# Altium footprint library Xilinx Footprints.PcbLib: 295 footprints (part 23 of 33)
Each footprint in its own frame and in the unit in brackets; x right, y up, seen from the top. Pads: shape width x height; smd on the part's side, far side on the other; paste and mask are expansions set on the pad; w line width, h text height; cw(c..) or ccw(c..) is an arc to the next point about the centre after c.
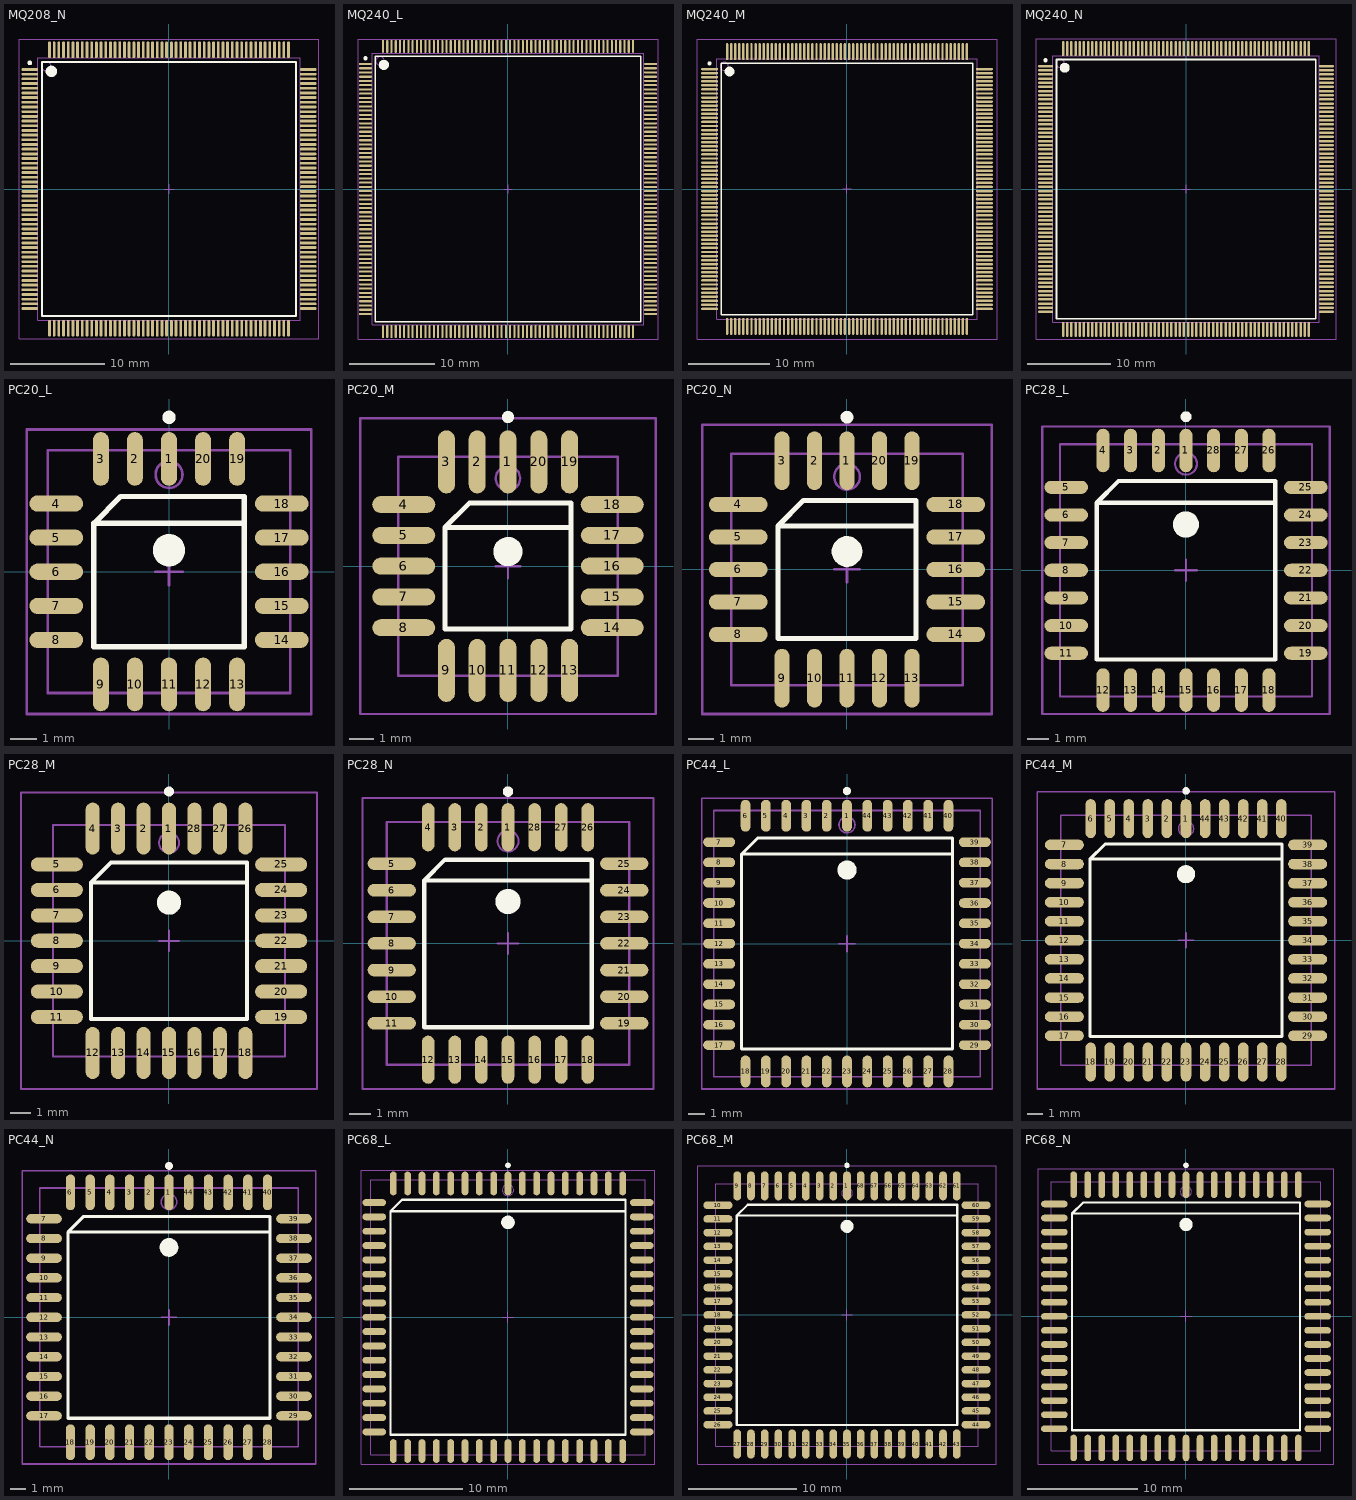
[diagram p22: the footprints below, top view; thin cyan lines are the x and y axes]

## MQ208_N [mm] "208-Pin Metal Quad Flat Pack (MQ208), IPC Medium Density"
height 4.1
pads (208):
  oval 1.8x0.3 smd: 1(-14.85,12.75) 2(-14.85,12.25) 3(-14.85,11.75) 4(-14.85,11.25) 5(-14.85,10.75) 6(-14.85,10.25) 7(-14.85,9.75) 8(-14.85,9.25) 9(-14.85,8.75) 10(-14.85,8.25) 11(-14.85,7.75) 12(-14.85,7.25) 13(-14.85,6.75) 14(-14.85,6.25) 15(-14.85,5.75) 16(-14.85,5.25) 17(-14.85,4.75) 18(-14.85,4.25) 19(-14.85,3.75) 20(-14.85,3.25) 21(-14.85,2.75) 22(-14.85,2.25) 23(-14.85,1.75) 24(-14.85,1.25) 25(-14.85,0.75) 26(-14.85,0.25) 27(-14.85,-0.25) 28(-14.85,-0.75) 29(-14.85,-1.25) 30(-14.85,-1.75) 31(-14.85,-2.25) 32(-14.85,-2.75) 33(-14.85,-3.25) 34(-14.85,-3.75) 35(-14.85,-4.25) 36(-14.85,-4.75) 37(-14.85,-5.25) 38(-14.85,-5.75) 39(-14.85,-6.25) 40(-14.85,-6.75) 41(-14.85,-7.25) 42(-14.85,-7.75) 43(-14.85,-8.25) 44(-14.85,-8.75) 45(-14.85,-9.25) 46(-14.85,-9.75) 47(-14.85,-10.25) 48(-14.85,-10.75) 49(-14.85,-11.25) 50(-14.85,-11.75) 51(-14.85,-12.25) 52(-14.85,-12.75) 105(14.85,-12.75) 106(14.85,-12.25) 107(14.85,-11.75) 108(14.85,-11.25) 109(14.85,-10.75) 110(14.85,-10.25) 111(14.85,-9.75) 112(14.85,-9.25) 113(14.85,-8.75) 114(14.85,-8.25) 115(14.85,-7.75) 116(14.85,-7.25) 117(14.85,-6.75) 118(14.85,-6.25) 119(14.85,-5.75) 120(14.85,-5.25) 121(14.85,-4.75) 122(14.85,-4.25) 123(14.85,-3.75) 124(14.85,-3.25) 125(14.85,-2.75) 126(14.85,-2.25) 127(14.85,-1.75) 128(14.85,-1.25) 129(14.85,-0.75) 130(14.85,-0.25) 131(14.85,0.25) 132(14.85,0.75) 133(14.85,1.25) 134(14.85,1.75) 135(14.85,2.25) 136(14.85,2.75) 137(14.85,3.25) 138(14.85,3.75) 139(14.85,4.25) 140(14.85,4.75) 141(14.85,5.25) 142(14.85,5.75) 143(14.85,6.25) 144(14.85,6.75) 145(14.85,7.25) 146(14.85,7.75) 147(14.85,8.25) 148(14.85,8.75) 149(14.85,9.25) 150(14.85,9.75) 151(14.85,10.25) 152(14.85,10.75) 153(14.85,11.25) 154(14.85,11.75) 155(14.85,12.25) 156(14.85,12.75)
  oval 0.3x1.8 smd: 53(-12.75,-14.85) 54(-12.25,-14.85) 55(-11.75,-14.85) 56(-11.25,-14.85) 57(-10.75,-14.85) 58(-10.25,-14.85) 59(-9.75,-14.85) 60(-9.25,-14.85) 61(-8.75,-14.85) 62(-8.25,-14.85) 63(-7.75,-14.85) 64(-7.25,-14.85) 65(-6.75,-14.85) 66(-6.25,-14.85) 67(-5.75,-14.85) 68(-5.25,-14.85) 69(-4.75,-14.85) 70(-4.25,-14.85) 71(-3.75,-14.85) 72(-3.25,-14.85) 73(-2.75,-14.85) 74(-2.25,-14.85) 75(-1.75,-14.85) 76(-1.25,-14.85) 77(-0.75,-14.85) 78(-0.25,-14.85) 79(0.25,-14.85) 80(0.75,-14.85) 81(1.25,-14.85) 82(1.75,-14.85) 83(2.25,-14.85) 84(2.75,-14.85) 85(3.25,-14.85) 86(3.75,-14.85) 87(4.25,-14.85) 88(4.75,-14.85) 89(5.25,-14.85) 90(5.75,-14.85) 91(6.25,-14.85) 92(6.75,-14.85) 93(7.25,-14.85) 94(7.75,-14.85) 95(8.25,-14.85) 96(8.75,-14.85) 97(9.25,-14.85) 98(9.75,-14.85) 99(10.25,-14.85) 100(10.75,-14.85) 101(11.25,-14.85) 102(11.75,-14.85) 103(12.25,-14.85) 104(12.75,-14.85) 157(12.75,14.85) 158(12.25,14.85) 159(11.75,14.85) 160(11.25,14.85) 161(10.75,14.85) 162(10.25,14.85) 163(9.75,14.85) 164(9.25,14.85) 165(8.75,14.85) 166(8.25,14.85) 167(7.75,14.85) 168(7.25,14.85) 169(6.75,14.85) 170(6.25,14.85) 171(5.75,14.85) 172(5.25,14.85) 173(4.75,14.85) 174(4.25,14.85) 175(3.75,14.85) 176(3.25,14.85) 177(2.75,14.85) 178(2.25,14.85) 179(1.75,14.85) 180(1.25,14.85) 181(0.75,14.85) 182(0.25,14.85) 183(-0.25,14.85) 184(-0.75,14.85) 185(-1.25,14.85) 186(-1.75,14.85) 187(-2.25,14.85) 188(-2.75,14.85) 189(-3.25,14.85) 190(-3.75,14.85) 191(-4.25,14.85) 192(-4.75,14.85) 193(-5.25,14.85) 194(-5.75,14.85) 195(-6.25,14.85) 196(-6.75,14.85) 197(-7.25,14.85) 198(-7.75,14.85) 199(-8.25,14.85) 200(-8.75,14.85) 201(-9.25,14.85) 202(-9.75,14.85) 203(-10.25,14.85) 204(-10.75,14.85) 205(-11.25,14.85) 206(-11.75,14.85) 207(-12.25,14.85) 208(-12.75,14.85)
Top Overlay:
  circle w0.6: c-12.55,12.55 r0.3
  circle w0.25: c-14.85,13.45 r0.125
  lines w0.2: -13.55,-13.55 13.55,-13.55 13.55,13.55 -13.55,13.55 -13.55,-13.55
Mechanical 13:
  circle w0.1: c-13.1,13.1 r0.5
  lines w0.1: -14,-14 14,-14 14,14 -14,14 -14,-14
Mechanical 15:
  lines w0.1: -0.5,0 0.5,0 ; 0,-0.5 0,0.5 ; -16,-16 16,-16 16,16 -16,16 -16,-16
3D body: height 4.1, standoff 0, extent -14,-14 14,14

## MQ240_L [mm] "240-Pin Metal Quad Flat Pack (MQ240), IPC High Density"
height 3.74
pads (240):
  oval 1.55x0.25 smd: 1(-16.825,14.75) 2(-16.825,14.25) 3(-16.825,13.75) 4(-16.825,13.25) 5(-16.825,12.75) 6(-16.825,12.25) 7(-16.825,11.75) 8(-16.825,11.25) 9(-16.825,10.75) 10(-16.825,10.25) 11(-16.825,9.75) 12(-16.825,9.25) 13(-16.825,8.75) 14(-16.825,8.25) 15(-16.825,7.75) 16(-16.825,7.25) 17(-16.825,6.75) 18(-16.825,6.25) 19(-16.825,5.75) 20(-16.825,5.25) 21(-16.825,4.75) 22(-16.825,4.25) 23(-16.825,3.75) 24(-16.825,3.25) 25(-16.825,2.75) 26(-16.825,2.25) 27(-16.825,1.75) 28(-16.825,1.25) 29(-16.825,0.75) 30(-16.825,0.25) 31(-16.825,-0.25) 32(-16.825,-0.75) 33(-16.825,-1.25) 34(-16.825,-1.75) 35(-16.825,-2.25) 36(-16.825,-2.75) 37(-16.825,-3.25) 38(-16.825,-3.75) 39(-16.825,-4.25) 40(-16.825,-4.75) 41(-16.825,-5.25) 42(-16.825,-5.75) 43(-16.825,-6.25) 44(-16.825,-6.75) 45(-16.825,-7.25) 46(-16.825,-7.75) 47(-16.825,-8.25) 48(-16.825,-8.75) 49(-16.825,-9.25) 50(-16.825,-9.75) 51(-16.825,-10.25) 52(-16.825,-10.75) 53(-16.825,-11.25) 54(-16.825,-11.75) 55(-16.825,-12.25) 56(-16.825,-12.75) 57(-16.825,-13.25) 58(-16.825,-13.75) 59(-16.825,-14.25) 60(-16.825,-14.75) 121(16.825,-14.75) 122(16.825,-14.25) 123(16.825,-13.75) 124(16.825,-13.25) 125(16.825,-12.75) 126(16.825,-12.25) 127(16.825,-11.75) 128(16.825,-11.25) 129(16.825,-10.75) 130(16.825,-10.25) 131(16.825,-9.75) 132(16.825,-9.25) 133(16.825,-8.75) 134(16.825,-8.25) 135(16.825,-7.75) 136(16.825,-7.25) 137(16.825,-6.75) 138(16.825,-6.25) 139(16.825,-5.75) 140(16.825,-5.25) 141(16.825,-4.75) 142(16.825,-4.25) 143(16.825,-3.75) 144(16.825,-3.25) 145(16.825,-2.75) 146(16.825,-2.25) 147(16.825,-1.75) 148(16.825,-1.25) 149(16.825,-0.75) 150(16.825,-0.25) 151(16.825,0.25) 152(16.825,0.75) 153(16.825,1.25) 154(16.825,1.75) 155(16.825,2.25) 156(16.825,2.75) 157(16.825,3.25) 158(16.825,3.75) 159(16.825,4.25) 160(16.825,4.75) 161(16.825,5.25) 162(16.825,5.75) 163(16.825,6.25) 164(16.825,6.75) 165(16.825,7.25) 166(16.825,7.75) 167(16.825,8.25) 168(16.825,8.75) 169(16.825,9.25) 170(16.825,9.75) 171(16.825,10.25) 172(16.825,10.75) 173(16.825,11.25) 174(16.825,11.75) 175(16.825,12.25) 176(16.825,12.75) 177(16.825,13.25) 178(16.825,13.75) 179(16.825,14.25) 180(16.825,14.75)
  oval 0.25x1.55 smd: 61(-14.75,-16.825) 62(-14.25,-16.825) 63(-13.75,-16.825) 64(-13.25,-16.825) 65(-12.75,-16.825) 66(-12.25,-16.825) 67(-11.75,-16.825) 68(-11.25,-16.825) 69(-10.75,-16.825) 70(-10.25,-16.825) 71(-9.75,-16.825) 72(-9.25,-16.825) 73(-8.75,-16.825) 74(-8.25,-16.825) 75(-7.75,-16.825) 76(-7.25,-16.825) 77(-6.75,-16.825) 78(-6.25,-16.825) 79(-5.75,-16.825) 80(-5.25,-16.825) 81(-4.75,-16.825) 82(-4.25,-16.825) 83(-3.75,-16.825) 84(-3.25,-16.825) 85(-2.75,-16.825) 86(-2.25,-16.825) 87(-1.75,-16.825) 88(-1.25,-16.825) 89(-0.75,-16.825) 90(-0.25,-16.825) 91(0.25,-16.825) 92(0.75,-16.825) 93(1.25,-16.825) 94(1.75,-16.825) 95(2.25,-16.825) 96(2.75,-16.825) 97(3.25,-16.825) 98(3.75,-16.825) 99(4.25,-16.825) 100(4.75,-16.825) 101(5.25,-16.825) 102(5.75,-16.825) 103(6.25,-16.825) 104(6.75,-16.825) 105(7.25,-16.825) 106(7.75,-16.825) 107(8.25,-16.825) 108(8.75,-16.825) 109(9.25,-16.825) 110(9.75,-16.825) 111(10.25,-16.825) 112(10.75,-16.825) 113(11.25,-16.825) 114(11.75,-16.825) 115(12.25,-16.825) 116(12.75,-16.825) 117(13.25,-16.825) 118(13.75,-16.825) 119(14.25,-16.825) 120(14.75,-16.825) 181(14.75,16.825) 182(14.25,16.825) 183(13.75,16.825) 184(13.25,16.825) 185(12.75,16.825) 186(12.25,16.825) 187(11.75,16.825) 188(11.25,16.825) 189(10.75,16.825) 190(10.25,16.825) 191(9.75,16.825) 192(9.25,16.825) 193(8.75,16.825) 194(8.25,16.825) 195(7.75,16.825) 196(7.25,16.825) 197(6.75,16.825) 198(6.25,16.825) 199(5.75,16.825) 200(5.25,16.825) 201(4.75,16.825) 202(4.25,16.825) 203(3.75,16.825) 204(3.25,16.825) 205(2.75,16.825) 206(2.25,16.825) 207(1.75,16.825) 208(1.25,16.825) 209(0.75,16.825) 210(0.25,16.825) 211(-0.25,16.825) 212(-0.75,16.825) 213(-1.25,16.825) 214(-1.75,16.825) 215(-2.25,16.825) 216(-2.75,16.825) 217(-3.25,16.825) 218(-3.75,16.825) 219(-4.25,16.825) 220(-4.75,16.825) 221(-5.25,16.825) 222(-5.75,16.825) 223(-6.25,16.825) 224(-6.75,16.825) 225(-7.25,16.825) 226(-7.75,16.825) 227(-8.25,16.825) 228(-8.75,16.825) 229(-9.25,16.825) 230(-9.75,16.825) 231(-10.25,16.825) 232(-10.75,16.825) 233(-11.25,16.825) 234(-11.75,16.825) 235(-12.25,16.825) 236(-12.75,16.825) 237(-13.25,16.825) 238(-13.75,16.825) 239(-14.25,16.825) 240(-14.75,16.825)
Top Overlay:
  circle w0.6: c-14.65,14.65 r0.3
  circle w0.25: c-16.825,15.425 r0.125
  lines w0.2: -15.65,-15.65 15.65,-15.65 15.65,15.65 -15.65,15.65 -15.65,-15.65
Mechanical 13:
  circle w0.1: c-15.1,15.1 r0.5
  lines w0.1: -16,-16 16,-16 16,16 -16,16 -16,-16
Mechanical 15:
  lines w0.1: -0.5,0 0.5,0 ; 0,-0.5 0,0.5 ; -17.7,-17.7 17.7,-17.7 17.7,17.7 -17.7,17.7 -17.7,-17.7
3D body: height 3.74, standoff 0, extent -16,-16 16,16

## MQ240_M [mm] "240-Pin Metal Quad Flat Pack (MQ240), IPC Low Density"
height 3.74
pads (240):
  oval 2.1x0.3 smd: 1(-16.9,14.75) 2(-16.9,14.25) 3(-16.9,13.75) 4(-16.9,13.25) 5(-16.9,12.75) 6(-16.9,12.25) 7(-16.9,11.75) 8(-16.9,11.25) 9(-16.9,10.75) 10(-16.9,10.25) 11(-16.9,9.75) 12(-16.9,9.25) 13(-16.9,8.75) 14(-16.9,8.25) 15(-16.9,7.75) 16(-16.9,7.25) 17(-16.9,6.75) 18(-16.9,6.25) 19(-16.9,5.75) 20(-16.9,5.25) 21(-16.9,4.75) 22(-16.9,4.25) 23(-16.9,3.75) 24(-16.9,3.25) 25(-16.9,2.75) 26(-16.9,2.25) 27(-16.9,1.75) 28(-16.9,1.25) 29(-16.9,0.75) 30(-16.9,0.25) 31(-16.9,-0.25) 32(-16.9,-0.75) 33(-16.9,-1.25) 34(-16.9,-1.75) 35(-16.9,-2.25) 36(-16.9,-2.75) 37(-16.9,-3.25) 38(-16.9,-3.75) 39(-16.9,-4.25) 40(-16.9,-4.75) 41(-16.9,-5.25) 42(-16.9,-5.75) 43(-16.9,-6.25) 44(-16.9,-6.75) 45(-16.9,-7.25) 46(-16.9,-7.75) 47(-16.9,-8.25) 48(-16.9,-8.75) 49(-16.9,-9.25) 50(-16.9,-9.75) 51(-16.9,-10.25) 52(-16.9,-10.75) 53(-16.9,-11.25) 54(-16.9,-11.75) 55(-16.9,-12.25) 56(-16.9,-12.75) 57(-16.9,-13.25) 58(-16.9,-13.75) 59(-16.9,-14.25) 60(-16.9,-14.75) 121(16.9,-14.75) 122(16.9,-14.25) 123(16.9,-13.75) 124(16.9,-13.25) 125(16.9,-12.75) 126(16.9,-12.25) 127(16.9,-11.75) 128(16.9,-11.25) 129(16.9,-10.75) 130(16.9,-10.25) 131(16.9,-9.75) 132(16.9,-9.25) 133(16.9,-8.75) 134(16.9,-8.25) 135(16.9,-7.75) 136(16.9,-7.25) 137(16.9,-6.75) 138(16.9,-6.25) 139(16.9,-5.75) 140(16.9,-5.25) 141(16.9,-4.75) 142(16.9,-4.25) 143(16.9,-3.75) 144(16.9,-3.25) 145(16.9,-2.75) 146(16.9,-2.25) 147(16.9,-1.75) 148(16.9,-1.25) 149(16.9,-0.75) 150(16.9,-0.25) 151(16.9,0.25) 152(16.9,0.75) 153(16.9,1.25) 154(16.9,1.75) 155(16.9,2.25) 156(16.9,2.75) 157(16.9,3.25) 158(16.9,3.75) 159(16.9,4.25) 160(16.9,4.75) 161(16.9,5.25) 162(16.9,5.75) 163(16.9,6.25) 164(16.9,6.75) 165(16.9,7.25) 166(16.9,7.75) 167(16.9,8.25) 168(16.9,8.75) 169(16.9,9.25) 170(16.9,9.75) 171(16.9,10.25) 172(16.9,10.75) 173(16.9,11.25) 174(16.9,11.75) 175(16.9,12.25) 176(16.9,12.75) 177(16.9,13.25) 178(16.9,13.75) 179(16.9,14.25) 180(16.9,14.75)
  oval 0.3x2.1 smd: 61(-14.75,-16.9) 62(-14.25,-16.9) 63(-13.75,-16.9) 64(-13.25,-16.9) 65(-12.75,-16.9) 66(-12.25,-16.9) 67(-11.75,-16.9) 68(-11.25,-16.9) 69(-10.75,-16.9) 70(-10.25,-16.9) 71(-9.75,-16.9) 72(-9.25,-16.9) 73(-8.75,-16.9) 74(-8.25,-16.9) 75(-7.75,-16.9) 76(-7.25,-16.9) 77(-6.75,-16.9) 78(-6.25,-16.9) 79(-5.75,-16.9) 80(-5.25,-16.9) 81(-4.75,-16.9) 82(-4.25,-16.9) 83(-3.75,-16.9) 84(-3.25,-16.9) 85(-2.75,-16.9) 86(-2.25,-16.9) 87(-1.75,-16.9) 88(-1.25,-16.9) 89(-0.75,-16.9) 90(-0.25,-16.9) 91(0.25,-16.9) 92(0.75,-16.9) 93(1.25,-16.9) 94(1.75,-16.9) 95(2.25,-16.9) 96(2.75,-16.9) 97(3.25,-16.9) 98(3.75,-16.9) 99(4.25,-16.9) 100(4.75,-16.9) 101(5.25,-16.9) 102(5.75,-16.9) 103(6.25,-16.9) 104(6.75,-16.9) 105(7.25,-16.9) 106(7.75,-16.9) 107(8.25,-16.9) 108(8.75,-16.9) 109(9.25,-16.9) 110(9.75,-16.9) 111(10.25,-16.9) 112(10.75,-16.9) 113(11.25,-16.9) 114(11.75,-16.9) 115(12.25,-16.9) 116(12.75,-16.9) 117(13.25,-16.9) 118(13.75,-16.9) 119(14.25,-16.9) 120(14.75,-16.9) 181(14.75,16.9) 182(14.25,16.9) 183(13.75,16.9) 184(13.25,16.9) 185(12.75,16.9) 186(12.25,16.9) 187(11.75,16.9) 188(11.25,16.9) 189(10.75,16.9) 190(10.25,16.9) 191(9.75,16.9) 192(9.25,16.9) 193(8.75,16.9) 194(8.25,16.9) 195(7.75,16.9) 196(7.25,16.9) 197(6.75,16.9) 198(6.25,16.9) 199(5.75,16.9) 200(5.25,16.9) 201(4.75,16.9) 202(4.25,16.9) 203(3.75,16.9) 204(3.25,16.9) 205(2.75,16.9) 206(2.25,16.9) 207(1.75,16.9) 208(1.25,16.9) 209(0.75,16.9) 210(0.25,16.9) 211(-0.25,16.9) 212(-0.75,16.9) 213(-1.25,16.9) 214(-1.75,16.9) 215(-2.25,16.9) 216(-2.75,16.9) 217(-3.25,16.9) 218(-3.75,16.9) 219(-4.25,16.9) 220(-4.75,16.9) 221(-5.25,16.9) 222(-5.75,16.9) 223(-6.25,16.9) 224(-6.75,16.9) 225(-7.25,16.9) 226(-7.75,16.9) 227(-8.25,16.9) 228(-8.75,16.9) 229(-9.25,16.9) 230(-9.75,16.9) 231(-10.25,16.9) 232(-10.75,16.9) 233(-11.25,16.9) 234(-11.75,16.9) 235(-12.25,16.9) 236(-12.75,16.9) 237(-13.25,16.9) 238(-13.75,16.9) 239(-14.25,16.9) 240(-14.75,16.9)
Top Overlay:
  circle w0.6: c-14.45,14.45 r0.3
  circle w0.25: c-16.9,15.45 r0.125
  lines w0.2: -15.45,-15.45 15.45,-15.45 15.45,15.45 -15.45,15.45 -15.45,-15.45
Mechanical 13:
  circle w0.1: c-15.1,15.1 r0.5
  lines w0.1: -16,-16 16,-16 16,16 -16,16 -16,-16
Mechanical 15:
  lines w0.1: -0.5,0 0.5,0 ; 0,-0.5 0,0.5 ; -18.45,-18.45 18.45,-18.45 18.45,18.45 -18.45,18.45 -18.45,-18.45
3D body: height 3.74, standoff 0, extent -16,-16 16,16

## MQ240_N [mm] "240-Pin Metal Quad Flat Pack (MQ240), IPC Medium Density"
height 3.74
pads (240):
  oval 1.8x0.3 smd: 1(-16.85,14.75) 2(-16.85,14.25) 3(-16.85,13.75) 4(-16.85,13.25) 5(-16.85,12.75) 6(-16.85,12.25) 7(-16.85,11.75) 8(-16.85,11.25) 9(-16.85,10.75) 10(-16.85,10.25) 11(-16.85,9.75) 12(-16.85,9.25) 13(-16.85,8.75) 14(-16.85,8.25) 15(-16.85,7.75) 16(-16.85,7.25) 17(-16.85,6.75) 18(-16.85,6.25) 19(-16.85,5.75) 20(-16.85,5.25) 21(-16.85,4.75) 22(-16.85,4.25) 23(-16.85,3.75) 24(-16.85,3.25) 25(-16.85,2.75) 26(-16.85,2.25) 27(-16.85,1.75) 28(-16.85,1.25) 29(-16.85,0.75) 30(-16.85,0.25) 31(-16.85,-0.25) 32(-16.85,-0.75) 33(-16.85,-1.25) 34(-16.85,-1.75) 35(-16.85,-2.25) 36(-16.85,-2.75) 37(-16.85,-3.25) 38(-16.85,-3.75) 39(-16.85,-4.25) 40(-16.85,-4.75) 41(-16.85,-5.25) 42(-16.85,-5.75) 43(-16.85,-6.25) 44(-16.85,-6.75) 45(-16.85,-7.25) 46(-16.85,-7.75) 47(-16.85,-8.25) 48(-16.85,-8.75) 49(-16.85,-9.25) 50(-16.85,-9.75) 51(-16.85,-10.25) 52(-16.85,-10.75) 53(-16.85,-11.25) 54(-16.85,-11.75) 55(-16.85,-12.25) 56(-16.85,-12.75) 57(-16.85,-13.25) 58(-16.85,-13.75) 59(-16.85,-14.25) 60(-16.85,-14.75) 121(16.85,-14.75) 122(16.85,-14.25) 123(16.85,-13.75) 124(16.85,-13.25) 125(16.85,-12.75) 126(16.85,-12.25) 127(16.85,-11.75) 128(16.85,-11.25) 129(16.85,-10.75) 130(16.85,-10.25) 131(16.85,-9.75) 132(16.85,-9.25) 133(16.85,-8.75) 134(16.85,-8.25) 135(16.85,-7.75) 136(16.85,-7.25) 137(16.85,-6.75) 138(16.85,-6.25) 139(16.85,-5.75) 140(16.85,-5.25) 141(16.85,-4.75) 142(16.85,-4.25) 143(16.85,-3.75) 144(16.85,-3.25) 145(16.85,-2.75) 146(16.85,-2.25) 147(16.85,-1.75) 148(16.85,-1.25) 149(16.85,-0.75) 150(16.85,-0.25) 151(16.85,0.25) 152(16.85,0.75) 153(16.85,1.25) 154(16.85,1.75) 155(16.85,2.25) 156(16.85,2.75) 157(16.85,3.25) 158(16.85,3.75) 159(16.85,4.25) 160(16.85,4.75) 161(16.85,5.25) 162(16.85,5.75) 163(16.85,6.25) 164(16.85,6.75) 165(16.85,7.25) 166(16.85,7.75) 167(16.85,8.25) 168(16.85,8.75) 169(16.85,9.25) 170(16.85,9.75) 171(16.85,10.25) 172(16.85,10.75) 173(16.85,11.25) 174(16.85,11.75) 175(16.85,12.25) 176(16.85,12.75) 177(16.85,13.25) 178(16.85,13.75) 179(16.85,14.25) 180(16.85,14.75)
  oval 0.3x1.8 smd: 61(-14.75,-16.85) 62(-14.25,-16.85) 63(-13.75,-16.85) 64(-13.25,-16.85) 65(-12.75,-16.85) 66(-12.25,-16.85) 67(-11.75,-16.85) 68(-11.25,-16.85) 69(-10.75,-16.85) 70(-10.25,-16.85) 71(-9.75,-16.85) 72(-9.25,-16.85) 73(-8.75,-16.85) 74(-8.25,-16.85) 75(-7.75,-16.85) 76(-7.25,-16.85) 77(-6.75,-16.85) 78(-6.25,-16.85) 79(-5.75,-16.85) 80(-5.25,-16.85) 81(-4.75,-16.85) 82(-4.25,-16.85) 83(-3.75,-16.85) 84(-3.25,-16.85) 85(-2.75,-16.85) 86(-2.25,-16.85) 87(-1.75,-16.85) 88(-1.25,-16.85) 89(-0.75,-16.85) 90(-0.25,-16.85) 91(0.25,-16.85) 92(0.75,-16.85) 93(1.25,-16.85) 94(1.75,-16.85) 95(2.25,-16.85) 96(2.75,-16.85) 97(3.25,-16.85) 98(3.75,-16.85) 99(4.25,-16.85) 100(4.75,-16.85) 101(5.25,-16.85) 102(5.75,-16.85) 103(6.25,-16.85) 104(6.75,-16.85) 105(7.25,-16.85) 106(7.75,-16.85) 107(8.25,-16.85) 108(8.75,-16.85) 109(9.25,-16.85) 110(9.75,-16.85) 111(10.25,-16.85) 112(10.75,-16.85) 113(11.25,-16.85) 114(11.75,-16.85) 115(12.25,-16.85) 116(12.75,-16.85) 117(13.25,-16.85) 118(13.75,-16.85) 119(14.25,-16.85) 120(14.75,-16.85) 181(14.75,16.85) 182(14.25,16.85) 183(13.75,16.85) 184(13.25,16.85) 185(12.75,16.85) 186(12.25,16.85) 187(11.75,16.85) 188(11.25,16.85) 189(10.75,16.85) 190(10.25,16.85) 191(9.75,16.85) 192(9.25,16.85) 193(8.75,16.85) 194(8.25,16.85) 195(7.75,16.85) 196(7.25,16.85) 197(6.75,16.85) 198(6.25,16.85) 199(5.75,16.85) 200(5.25,16.85) 201(4.75,16.85) 202(4.25,16.85) 203(3.75,16.85) 204(3.25,16.85) 205(2.75,16.85) 206(2.25,16.85) 207(1.75,16.85) 208(1.25,16.85) 209(0.75,16.85) 210(0.25,16.85) 211(-0.25,16.85) 212(-0.75,16.85) 213(-1.25,16.85) 214(-1.75,16.85) 215(-2.25,16.85) 216(-2.75,16.85) 217(-3.25,16.85) 218(-3.75,16.85) 219(-4.25,16.85) 220(-4.75,16.85) 221(-5.25,16.85) 222(-5.75,16.85) 223(-6.25,16.85) 224(-6.75,16.85) 225(-7.25,16.85) 226(-7.75,16.85) 227(-8.25,16.85) 228(-8.75,16.85) 229(-9.25,16.85) 230(-9.75,16.85) 231(-10.25,16.85) 232(-10.75,16.85) 233(-11.25,16.85) 234(-11.75,16.85) 235(-12.25,16.85) 236(-12.75,16.85) 237(-13.25,16.85) 238(-13.75,16.85) 239(-14.25,16.85) 240(-14.75,16.85)
Top Overlay:
  circle w0.6: c-14.55,14.55 r0.3
  circle w0.25: c-16.85,15.45 r0.125
  lines w0.2: -15.55,-15.55 15.55,-15.55 15.55,15.55 -15.55,15.55 -15.55,-15.55
Mechanical 13:
  circle w0.1: c-15.1,15.1 r0.5
  lines w0.1: -16,-16 16,-16 16,16 -16,16 -16,-16
Mechanical 15:
  lines w0.1: -0.5,0 0.5,0 ; 0,-0.5 0,0.5 ; -18,-18 18,-18 18,18 -18,18 -18,-18
3D body: height 3.74, standoff 0, extent -16,-16 16,16

## PC20_L [mm] "20-Pin Plastic Leaded Chip Carrier (PC20), IPC High Density"
height 4.58
pads (20):
  oval 0.6x2 smd: 1(0,4.2) 2(-1.27,4.2) 3(-2.54,4.2) 9(-2.54,-4.2) 10(-1.27,-4.2) 11(0,-4.2) 12(1.27,-4.2) 13(2.54,-4.2) 19(2.54,4.2) 20(1.27,4.2)
  oval 2x0.6 smd: 4(-4.2,2.54) 5(-4.2,1.27) 6(-4.2,0) 7(-4.2,-1.27) 8(-4.2,-2.54) 14(4.2,-2.54) 15(4.2,-1.27) 16(4.2,0) 17(4.2,1.27) 18(4.2,2.54)
Top Overlay:
  circle w0.25: c0,5.75 r0.125
  circle w0.6: c0,0.8 r0.3
  lines w0.2: 2.8,1.8 -2.8,1.8 ; -2.8,1.8 -1.8,2.8 2.8,2.8 2.8,-2.8 -2.8,-2.8 -2.8,1.8
Mechanical 13:
  circle w0.1: c0,3.62 r0.5
  lines w0.1: -4.52,-4.52 -4.52,4.52 4.52,4.52 4.52,-4.52 -4.52,-4.52
Mechanical 15:
  lines w0.1: -0.5,0 0.5,0 ; 0,-0.5 0,0.5 ; -5.3,-5.3 -5.3,5.3 5.3,5.3 5.3,-5.3 -5.3,-5.3
3D body: height 4.58, standoff 0, extent -4.52,-4.52 4.52,4.52

## PC20_M [mm] "20-Pin Plastic Leaded Chip Carrier (PC20), IPC Low Density"
height 4.58
pads (20):
  oval 0.7x2.6 smd: 1(0,4.3) 2(-1.27,4.3) 3(-2.54,4.3) 9(-2.54,-4.3) 10(-1.27,-4.3) 11(0,-4.3) 12(1.27,-4.3) 13(2.54,-4.3) 19(2.54,4.3) 20(1.27,4.3)
  oval 2.6x0.7 smd: 4(-4.3,2.54) 5(-4.3,1.27) 6(-4.3,0) 7(-4.3,-1.27) 8(-4.3,-2.54) 14(4.3,-2.54) 15(4.3,-1.27) 16(4.3,0) 17(4.3,1.27) 18(4.3,2.54)
Top Overlay:
  circle w0.25: c0,6.15 r0.125
  circle w0.6: c0,0.6 r0.3
  lines w0.2: 2.6,1.6 -2.6,1.6 ; -2.6,1.6 -1.6,2.6 2.6,2.6 2.6,-2.6 -2.6,-2.6 -2.6,1.6
Mechanical 13:
  circle w0.1: c0,3.62 r0.5
  lines w0.1: -4.52,-4.52 -4.52,4.52 4.52,4.52 4.52,-4.52 -4.52,-4.52
Mechanical 15:
  lines w0.1: -0.5,0 0.5,0 ; 0,-0.5 0,0.5 ; -6.1,-6.1 -6.1,6.1 6.1,6.1 6.1,-6.1 -6.1,-6.1
3D body: height 4.58, standoff 0, extent -4.52,-4.52 4.52,4.52

## PC20_N [mm] "20-Pin Plastic Leaded Chip Carrier (PC20), IPC Medium Density"
height 4.58
pads (20):
  oval 0.6x2.3 smd: 1(0,4.25) 2(-1.27,4.25) 3(-2.54,4.25) 9(-2.54,-4.25) 10(-1.27,-4.25) 11(0,-4.25) 12(1.27,-4.25) 13(2.54,-4.25) 19(2.54,4.25) 20(1.27,4.25)
  oval 2.3x0.6 smd: 4(-4.25,2.54) 5(-4.25,1.27) 6(-4.25,0) 7(-4.25,-1.27) 8(-4.25,-2.54) 14(4.25,-2.54) 15(4.25,-1.27) 16(4.25,0) 17(4.25,1.27) 18(4.25,2.54)
Top Overlay:
  circle w0.6: c0,0.7 r0.3
  circle w0.25: c0,5.95 r0.125
  lines w0.2: 2.7,1.7 -2.7,1.7 ; -2.7,1.7 -2.7,-2.7 2.7,-2.7 2.7,2.7 -1.7,2.7 -2.7,1.7
Mechanical 13:
  circle w0.1: c0,3.62 r0.5
  lines w0.1: -4.52,-4.52 4.52,-4.52 4.52,4.52 -4.52,4.52 -4.52,-4.52
Mechanical 15:
  lines w0.1: -0.5,0 0.5,0 ; 0,-0.5 0,0.5 ; -5.65,-5.65 5.65,-5.65 5.65,5.65 -5.65,5.65 -5.65,-5.65
3D body: height 4.58, standoff 0, extent -4.52,-4.52 4.52,4.52

## PC28_L [mm] "28-Pin Plastic Leaded Chip Carrier (PC28), IPC High Density"
height 4.58
pads (28):
  oval 0.6x2 smd: 1(0,5.5) 2(-1.27,5.5) 3(-2.54,5.5) 4(-3.81,5.5) 12(-3.81,-5.5) 13(-2.54,-5.5) 14(-1.27,-5.5) 15(0,-5.5) 16(1.27,-5.5) 17(2.54,-5.5) 18(3.81,-5.5) 26(3.81,5.5) 27(2.54,5.5) 28(1.27,5.5)
  oval 2x0.6 smd: 5(-5.5,3.81) 6(-5.5,2.54) 7(-5.5,1.27) 8(-5.5,0) 9(-5.5,-1.27) 10(-5.5,-2.54) 11(-5.5,-3.81) 19(5.5,-3.81) 20(5.5,-2.54) 21(5.5,-1.27) 22(5.5,0) 23(5.5,1.27) 24(5.5,2.54) 25(5.5,3.81)
Top Overlay:
  circle w0.25: c0,7.05 r0.125
  circle w0.6: c0,2.1 r0.3
  lines w0.2: 4.1,3.1 -4.1,3.1 ; -4.1,3.1 -3.1,4.1 4.1,4.1 4.1,-4.1 -4.1,-4.1 -4.1,3.1
Mechanical 13:
  circle w0.1: c0,4.89 r0.5
  lines w0.1: -5.79,-5.79 -5.79,5.79 5.79,5.79 5.79,-5.79 -5.79,-5.79
Mechanical 15:
  lines w0.1: -0.5,0 0.5,0 ; 0,-0.5 0,0.5 ; -6.6,-6.6 -6.6,6.6 6.6,6.6 6.6,-6.6 -6.6,-6.6
3D body: height 4.58, standoff 0, extent -5.79,-5.79 5.79,5.79

## PC28_M [mm] "28-Pin Plastic Leaded Chip Carrier (PC28), IPC Low Density"
height 4.58
pads (28):
  oval 0.7x2.6 smd: 1(0,5.6) 2(-1.27,5.6) 3(-2.54,5.6) 4(-3.81,5.6) 12(-3.81,-5.6) 13(-2.54,-5.6) 14(-1.27,-5.6) 15(0,-5.6) 16(1.27,-5.6) 17(2.54,-5.6) 18(3.81,-5.6) 26(3.81,5.6) 27(2.54,5.6) 28(1.27,5.6)
  oval 2.6x0.7 smd: 5(-5.6,3.81) 6(-5.6,2.54) 7(-5.6,1.27) 8(-5.6,0) 9(-5.6,-1.27) 10(-5.6,-2.54) 11(-5.6,-3.81) 19(5.6,-3.81) 20(5.6,-2.54) 21(5.6,-1.27) 22(5.6,0) 23(5.6,1.27) 24(5.6,2.54) 25(5.6,3.81)
Top Overlay:
  circle w0.25: c0,7.45 r0.125
  circle w0.6: c0,1.9 r0.3
  lines w0.2: 3.9,2.9 -3.9,2.9 ; -3.9,2.9 -2.9,3.9 3.9,3.9 3.9,-3.9 -3.9,-3.9 -3.9,2.9
Mechanical 13:
  circle w0.1: c0,4.89 r0.5
  lines w0.1: -5.79,-5.79 -5.79,5.79 5.79,5.79 5.79,-5.79 -5.79,-5.79
Mechanical 15:
  lines w0.1: -0.5,0 0.5,0 ; 0,-0.5 0,0.5 ; -7.4,-7.4 -7.4,7.4 7.4,7.4 7.4,-7.4 -7.4,-7.4
3D body: height 4.58, standoff 0, extent -5.79,-5.79 5.79,5.79

## PC28_N [mm] "28-Pin Plastic Leaded Chip Carrier (PC28), IPC Medium Density"
height 4.58
pads (28):
  oval 0.6x2.3 smd: 1(0,5.55) 2(-1.27,5.55) 3(-2.54,5.55) 4(-3.81,5.55) 12(-3.81,-5.55) 13(-2.54,-5.55) 14(-1.27,-5.55) 15(0,-5.55) 16(1.27,-5.55) 17(2.54,-5.55) 18(3.81,-5.55) 26(3.81,5.55) 27(2.54,5.55) 28(1.27,5.55)
  oval 2.3x0.6 smd: 5(-5.55,3.81) 6(-5.55,2.54) 7(-5.55,1.27) 8(-5.55,0) 9(-5.55,-1.27) 10(-5.55,-2.54) 11(-5.55,-3.81) 19(5.55,-3.81) 20(5.55,-2.54) 21(5.55,-1.27) 22(5.55,0) 23(5.55,1.27) 24(5.55,2.54) 25(5.55,3.81)
Top Overlay:
  circle w0.25: c0,7.25 r0.125
  circle w0.6: c0,2 r0.3
  lines w0.2: 4,3 -4,3 ; -4,3 -3,4 4,4 4,-4 -4,-4 -4,3
Mechanical 13:
  circle w0.1: c0,4.89 r0.5
  lines w0.1: -5.79,-5.79 -5.79,5.79 5.79,5.79 5.79,-5.79 -5.79,-5.79
Mechanical 15:
  lines w0.1: -0.5,0 0.5,0 ; 0,-0.5 0,0.5 ; -6.95,-6.95 -6.95,6.95 6.95,6.95 6.95,-6.95 -6.95,-6.95
3D body: height 4.58, standoff 0, extent -5.79,-5.79 5.79,5.79

## PC44_L [mm] "44-Pin Plastic Leaded Chip Carrier (PC44), IPC High Density"
height 4.58
pads (44):
  oval 0.6x2 smd: 1(0,8) 2(-1.27,8) 3(-2.54,8) 4(-3.81,8) 5(-5.08,8) 6(-6.35,8) 18(-6.35,-8) 19(-5.08,-8) 20(-3.81,-8) 21(-2.54,-8) 22(-1.27,-8) 23(0,-8) 24(1.27,-8) 25(2.54,-8) 26(3.81,-8) 27(5.08,-8) 28(6.35,-8) 40(6.35,8) 41(5.08,8) 42(3.81,8) 43(2.54,8) 44(1.27,8)
  oval 2x0.6 smd: 7(-8,6.35) 8(-8,5.08) 9(-8,3.81) 10(-8,2.54) 11(-8,1.27) 12(-8,0) 13(-8,-1.27) 14(-8,-2.54) 15(-8,-3.81) 16(-8,-5.08) 17(-8,-6.35) 29(8,-6.35) 30(8,-5.08) 31(8,-3.81) 32(8,-2.54) 33(8,-1.27) 34(8,0) 35(8,1.27) 36(8,2.54) 37(8,3.81) 38(8,5.08) 39(8,6.35)
Top Overlay:
  circle w0.25: c0,9.55 r0.125
  circle w0.6: c0,4.6 r0.3
  lines w0.2: 6.6,5.6 -6.6,5.6 ; -6.6,5.6 -5.6,6.6 6.6,6.6 6.6,-6.6 -6.6,-6.6 -6.6,5.6
Mechanical 13:
  circle w0.1: c0,7.43 r0.5
  lines w0.1: -8.33,-8.33 -8.33,8.33 8.33,8.33 8.33,-8.33 -8.33,-8.33
Mechanical 15:
  lines w0.1: -0.5,0 0.5,0 ; 0,-0.5 0,0.5 ; -9.1,-9.1 -9.1,9.1 9.1,9.1 9.1,-9.1 -9.1,-9.1
3D body: height 4.58, standoff 0, extent -8.33,-8.33 8.33,8.33

## PC44_M [mm] "44-Pin Plastic Leaded Chip Carrier (PC44), IPC Low Density"
height 4.58
pads (44):
  oval 0.7x2.6 smd: 1(0,8.1) 2(-1.27,8.1) 3(-2.54,8.1) 4(-3.81,8.1) 5(-5.08,8.1) 6(-6.35,8.1) 18(-6.35,-8.1) 19(-5.08,-8.1) 20(-3.81,-8.1) 21(-2.54,-8.1) 22(-1.27,-8.1) 23(0,-8.1) 24(1.27,-8.1) 25(2.54,-8.1) 26(3.81,-8.1) 27(5.08,-8.1) 28(6.35,-8.1) 40(6.35,8.1) 41(5.08,8.1) 42(3.81,8.1) 43(2.54,8.1) 44(1.27,8.1)
  oval 2.6x0.7 smd: 7(-8.1,6.35) 8(-8.1,5.08) 9(-8.1,3.81) 10(-8.1,2.54) 11(-8.1,1.27) 12(-8.1,0) 13(-8.1,-1.27) 14(-8.1,-2.54) 15(-8.1,-3.81) 16(-8.1,-5.08) 17(-8.1,-6.35) 29(8.1,-6.35) 30(8.1,-5.08) 31(8.1,-3.81) 32(8.1,-2.54) 33(8.1,-1.27) 34(8.1,0) 35(8.1,1.27) 36(8.1,2.54) 37(8.1,3.81) 38(8.1,5.08) 39(8.1,6.35)
Top Overlay:
  circle w0.25: c0,9.95 r0.125
  circle w0.6: c0,4.4 r0.3
  lines w0.2: 6.4,5.4 -6.4,5.4 ; -6.4,5.4 -5.4,6.4 6.4,6.4 6.4,-6.4 -6.4,-6.4 -6.4,5.4
Mechanical 13:
  circle w0.1: c0,7.43 r0.5
  lines w0.1: -8.33,-8.33 -8.33,8.33 8.33,8.33 8.33,-8.33 -8.33,-8.33
Mechanical 15:
  lines w0.1: -0.5,0 0.5,0 ; 0,-0.5 0,0.5 ; -9.9,-9.9 -9.9,9.9 9.9,9.9 9.9,-9.9 -9.9,-9.9
3D body: height 4.58, standoff 0, extent -8.33,-8.33 8.33,8.33

## PC44_N [mm] "44-Pin Plastic Leaded Chip Carrier (PC44), IPC Medium Density"
height 4.58
pads (44):
  oval 0.6x2.3 smd: 1(0,8.05) 2(-1.27,8.05) 3(-2.54,8.05) 4(-3.81,8.05) 5(-5.08,8.05) 6(-6.35,8.05) 18(-6.35,-8.05) 19(-5.08,-8.05) 20(-3.81,-8.05) 21(-2.54,-8.05) 22(-1.27,-8.05) 23(0,-8.05) 24(1.27,-8.05) 25(2.54,-8.05) 26(3.81,-8.05) 27(5.08,-8.05) 28(6.35,-8.05) 40(6.35,8.05) 41(5.08,8.05) 42(3.81,8.05) 43(2.54,8.05) 44(1.27,8.05)
  oval 2.3x0.6 smd: 7(-8.05,6.35) 8(-8.05,5.08) 9(-8.05,3.81) 10(-8.05,2.54) 11(-8.05,1.27) 12(-8.05,0) 13(-8.05,-1.27) 14(-8.05,-2.54) 15(-8.05,-3.81) 16(-8.05,-5.08) 17(-8.05,-6.35) 29(8.05,-6.35) 30(8.05,-5.08) 31(8.05,-3.81) 32(8.05,-2.54) 33(8.05,-1.27) 34(8.05,0) 35(8.05,1.27) 36(8.05,2.54) 37(8.05,3.81) 38(8.05,5.08) 39(8.05,6.35)
Top Overlay:
  circle w0.25: c0,9.75 r0.125
  circle w0.6: c0,4.5 r0.3
  lines w0.2: 6.5,5.5 -6.5,5.5 ; -6.5,5.5 -5.5,6.5 6.5,6.5 6.5,-6.5 -6.5,-6.5 -6.5,5.5
Mechanical 13:
  circle w0.1: c0,7.43 r0.5
  lines w0.1: -8.33,-8.33 -8.33,8.33 8.33,8.33 8.33,-8.33 -8.33,-8.33
Mechanical 15:
  lines w0.1: -0.5,0 0.5,0 ; 0,-0.5 0,0.5 ; -9.45,-9.45 -9.45,9.45 9.45,9.45 9.45,-9.45 -9.45,-9.45
3D body: height 4.58, standoff 0, extent -8.33,-8.33 8.33,8.33

## PC68_L [mm] "68-Pin Plastic Leaded Chip Carrier (PC68), IPC High Density"
height 5.08
pads (68):
  oval 0.6x2.1 smd: 1(0,11.85) 2(-1.27,11.85) 3(-2.54,11.85) 4(-3.81,11.85) 5(-5.08,11.85) 6(-6.35,11.85) 7(-7.62,11.85) 8(-8.89,11.85) 9(-10.16,11.85) 27(-10.16,-11.85) 28(-8.89,-11.85) 29(-7.62,-11.85) 30(-6.35,-11.85) 31(-5.08,-11.85) 32(-3.81,-11.85) 33(-2.54,-11.85) 34(-1.27,-11.85) 35(0,-11.85) 36(1.27,-11.85) 37(2.54,-11.85) 38(3.81,-11.85) 39(5.08,-11.85) 40(6.35,-11.85) 41(7.62,-11.85) 42(8.89,-11.85) 43(10.16,-11.85) 61(10.16,11.85) 62(8.89,11.85) 63(7.62,11.85) 64(6.35,11.85) 65(5.08,11.85) 66(3.81,11.85) 67(2.54,11.85) 68(1.27,11.85)
  oval 2.1x0.6 smd: 10(-11.85,10.16) 11(-11.85,8.89) 12(-11.85,7.62) 13(-11.85,6.35) 14(-11.85,5.08) 15(-11.85,3.81) 16(-11.85,2.54) 17(-11.85,1.27) 18(-11.85,0) 19(-11.85,-1.27) 20(-11.85,-2.54) 21(-11.85,-3.81) 22(-11.85,-5.08) 23(-11.85,-6.35) 24(-11.85,-7.62) 25(-11.85,-8.89) 26(-11.85,-10.16) 44(11.85,-10.16) 45(11.85,-8.89) 46(11.85,-7.62) 47(11.85,-6.35) 48(11.85,-5.08) 49(11.85,-3.81) 50(11.85,-2.54) 51(11.85,-1.27) 52(11.85,0) 53(11.85,1.27) 54(11.85,2.54) 55(11.85,3.81) 56(11.85,5.08) 57(11.85,6.35) 58(11.85,7.62) 59(11.85,8.89) 60(11.85,10.16)
Top Overlay:
  circle w0.6: c0,8.4 r0.3
  circle w0.25: c0,13.45 r0.125
  lines w0.2: 10.4,9.4 -10.4,9.4 ; -10.4,9.4 -10.4,-10.4 10.4,-10.4 10.4,10.4 -9.4,10.4 -10.4,9.4
Mechanical 13:
  circle w0.1: c0,11.265 r0.5
  lines w0.1: -12.165,-12.165 12.165,-12.165 12.165,12.165 -12.165,12.165 -12.165,-12.165
Mechanical 15:
  lines w0.1: -0.5,0 0.5,0 ; 0,-0.5 0,0.5 ; -13,-13 13,-13 13,13 -13,13 -13,-13
3D body: height 5.08, standoff 0, extent -12.165,-12.165 12.165,12.165

## PC68_M [mm] "68-Pin Plastic Leaded Chip Carrier (PC68), IPC Low Density"
height 5.08
pads (68):
  oval 0.7x2.7 smd: 1(0,11.95) 2(-1.27,11.95) 3(-2.54,11.95) 4(-3.81,11.95) 5(-5.08,11.95) 6(-6.35,11.95) 7(-7.62,11.95) 8(-8.89,11.95) 9(-10.16,11.95) 27(-10.16,-11.95) 28(-8.89,-11.95) 29(-7.62,-11.95) 30(-6.35,-11.95) 31(-5.08,-11.95) 32(-3.81,-11.95) 33(-2.54,-11.95) 34(-1.27,-11.95) 35(0,-11.95) 36(1.27,-11.95) 37(2.54,-11.95) 38(3.81,-11.95) 39(5.08,-11.95) 40(6.35,-11.95) 41(7.62,-11.95) 42(8.89,-11.95) 43(10.16,-11.95) 61(10.16,11.95) 62(8.89,11.95) 63(7.62,11.95) 64(6.35,11.95) 65(5.08,11.95) 66(3.81,11.95) 67(2.54,11.95) 68(1.27,11.95)
  oval 2.7x0.7 smd: 10(-11.95,10.16) 11(-11.95,8.89) 12(-11.95,7.62) 13(-11.95,6.35) 14(-11.95,5.08) 15(-11.95,3.81) 16(-11.95,2.54) 17(-11.95,1.27) 18(-11.95,0) 19(-11.95,-1.27) 20(-11.95,-2.54) 21(-11.95,-3.81) 22(-11.95,-5.08) 23(-11.95,-6.35) 24(-11.95,-7.62) 25(-11.95,-8.89) 26(-11.95,-10.16) 44(11.95,-10.16) 45(11.95,-8.89) 46(11.95,-7.62) 47(11.95,-6.35) 48(11.95,-5.08) 49(11.95,-3.81) 50(11.95,-2.54) 51(11.95,-1.27) 52(11.95,0) 53(11.95,1.27) 54(11.95,2.54) 55(11.95,3.81) 56(11.95,5.08) 57(11.95,6.35) 58(11.95,7.62) 59(11.95,8.89) 60(11.95,10.16)
Top Overlay:
  circle w0.25: c0,13.85 r0.125
  circle w0.6: c0,8.2 r0.3
  lines w0.2: 10.2,9.2 -10.2,9.2 ; -10.2,9.2 -9.2,10.2 10.2,10.2 10.2,-10.2 -10.2,-10.2 -10.2,9.2
Mechanical 13:
  circle w0.1: c0,11.265 r0.5
  lines w0.1: -12.165,-12.165 -12.165,12.165 12.165,12.165 12.165,-12.165 -12.165,-12.165
Mechanical 15:
  lines w0.1: -0.5,0 0.5,0 ; 0,-0.5 0,0.5 ; -13.8,-13.8 -13.8,13.8 13.8,13.8 13.8,-13.8 -13.8,-13.8
3D body: height 5.08, standoff 0, extent -12.165,-12.165 12.165,12.165

## PC68_N [mm] "68-Pin Plastic Leaded Chip Carrier (PC68), IPC Medium Density"
height 5.08
pads (68):
  oval 0.6x2.4 smd: 1(0,11.9) 2(-1.27,11.9) 3(-2.54,11.9) 4(-3.81,11.9) 5(-5.08,11.9) 6(-6.35,11.9) 7(-7.62,11.9) 8(-8.89,11.9) 9(-10.16,11.9) 27(-10.16,-11.9) 28(-8.89,-11.9) 29(-7.62,-11.9) 30(-6.35,-11.9) 31(-5.08,-11.9) 32(-3.81,-11.9) 33(-2.54,-11.9) 34(-1.27,-11.9) 35(0,-11.9) 36(1.27,-11.9) 37(2.54,-11.9) 38(3.81,-11.9) 39(5.08,-11.9) 40(6.35,-11.9) 41(7.62,-11.9) 42(8.89,-11.9) 43(10.16,-11.9) 61(10.16,11.9) 62(8.89,11.9) 63(7.62,11.9) 64(6.35,11.9) 65(5.08,11.9) 66(3.81,11.9) 67(2.54,11.9) 68(1.27,11.9)
  oval 2.4x0.6 smd: 10(-11.9,10.16) 11(-11.9,8.89) 12(-11.9,7.62) 13(-11.9,6.35) 14(-11.9,5.08) 15(-11.9,3.81) 16(-11.9,2.54) 17(-11.9,1.27) 18(-11.9,0) 19(-11.9,-1.27) 20(-11.9,-2.54) 21(-11.9,-3.81) 22(-11.9,-5.08) 23(-11.9,-6.35) 24(-11.9,-7.62) 25(-11.9,-8.89) 26(-11.9,-10.16) 44(11.9,-10.16) 45(11.9,-8.89) 46(11.9,-7.62) 47(11.9,-6.35) 48(11.9,-5.08) 49(11.9,-3.81) 50(11.9,-2.54) 51(11.9,-1.27) 52(11.9,0) 53(11.9,1.27) 54(11.9,2.54) 55(11.9,3.81) 56(11.9,5.08) 57(11.9,6.35) 58(11.9,7.62) 59(11.9,8.89) 60(11.9,10.16)
Top Overlay:
  circle w0.25: c0,13.65 r0.125
  circle w0.6: c0,8.3 r0.3
  lines w0.2: 10.3,9.3 -10.3,9.3 ; -10.3,9.3 -9.3,10.3 10.3,10.3 10.3,-10.3 -10.3,-10.3 -10.3,9.3
Mechanical 13:
  circle w0.1: c0,11.265 r0.5
  lines w0.1: -12.165,-12.165 -12.165,12.165 12.165,12.165 12.165,-12.165 -12.165,-12.165
Mechanical 15:
  lines w0.1: -0.5,0 0.5,0 ; 0,-0.5 0,0.5 ; -13.35,-13.35 -13.35,13.35 13.35,13.35 13.35,-13.35 -13.35,-13.35
3D body: height 5.08, standoff 0, extent -12.165,-12.165 12.165,12.165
